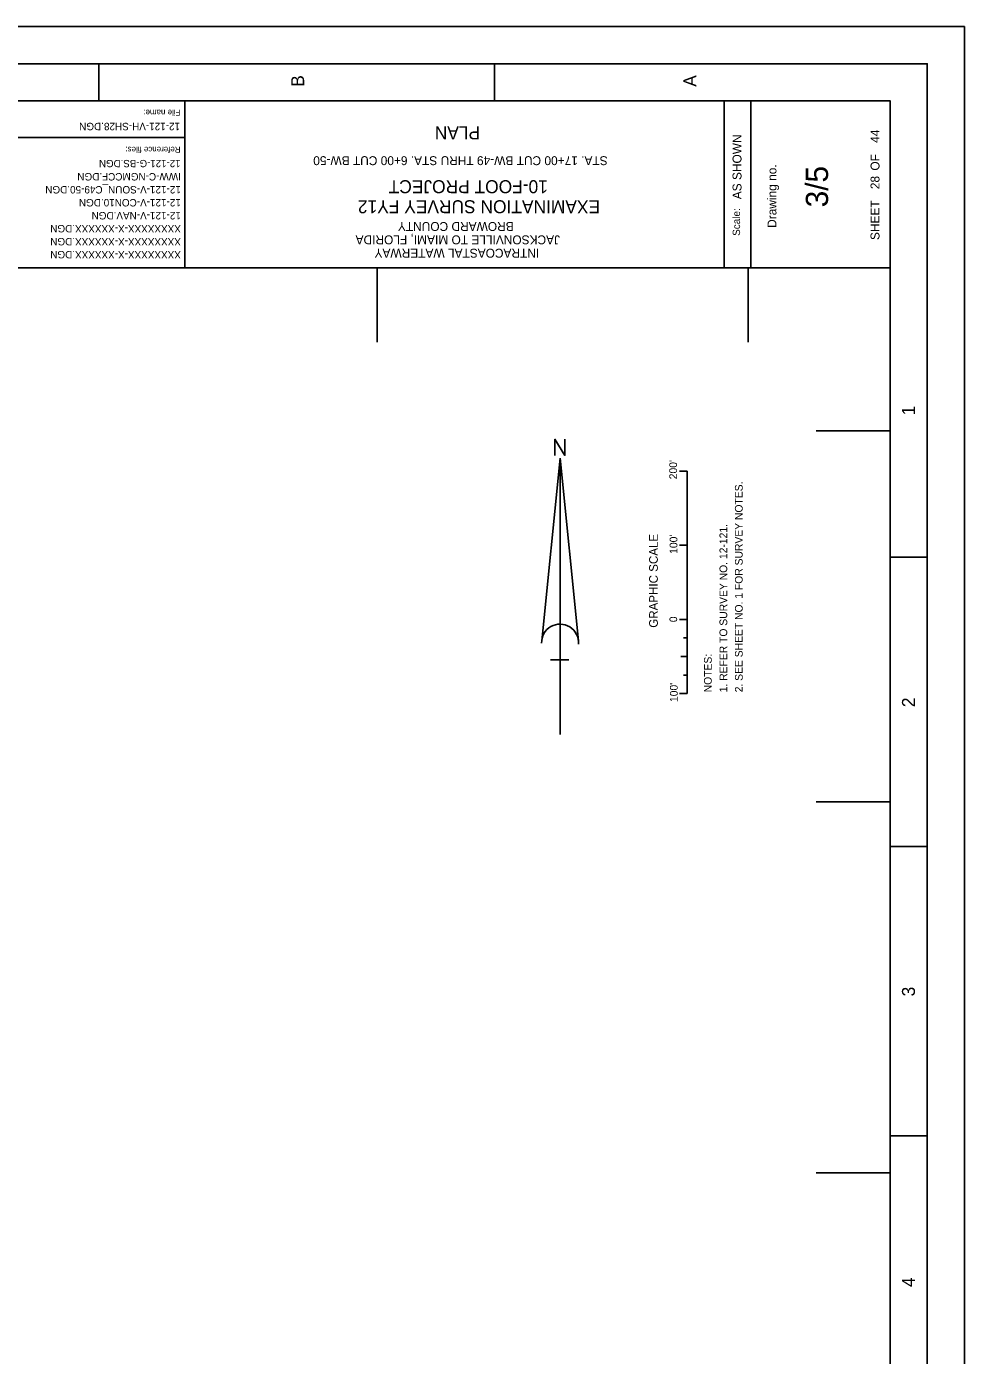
# Model space of a CAD drawing. Extents: x 943892 to 947291, y 640645 to 645045.
# Drawn here: x 946027 to 947291, y 643254 to 645045 of the extents above; entities that cross this region are included whole.
import ezdxf

# ---------------------------------------------------------------- set-up
doc = ezdxf.new("R2010")
doc.units = 0
for name, color, linetype in [('G-ANNO-NPLT', 7, 'Continuous'), ('G-ANNO-TEXT-DRWG', 7, 'Continuous'), ('G-ANNO-TEXT-PROJ', 7, 'Continuous'), ('G-ANNO-TEXT-TTLB', 7, 'Continuous'), ('G-ANNO-TTLB', 7, 'Continuous'), ('V-ANNO-NOTE', 7, 'Continuous'), ('V-ANNO-SYMB', 7, 'Continuous'), ('V-TOPO-COOR-STAT', 7, 'Continuous')]:
    doc.layers.add(name, color=color, linetype=linetype)

msp = doc.modelspace()

# ---------------------------------------------------------------- linework, layer by layer
at = {"layer": 'G-ANNO-NPLT'}
msp.add_lwpolyline([(943891.5, 640644.6), (943891.5, 645044.6), (947291.5, 645044.6), (947291.5, 640644.6)], close=True, dxfattribs=at)
msp.add_lwpolyline([(947241.5, 645044.7), (947291.5, 645044.7), (947291.5, 644994.7)], dxfattribs=at)
at = {"layer": 'G-ANNO-TTLB'}
for p, q in [((946124.9, 644994.6), (946124.9, 644944.6)), ((946658.2, 644994.6), (946658.2, 644944.6)), ((946240.7, 644719.6), (946240.7, 644944.6)), ((946967.7, 644719.6), (946967.7, 644944.6)), ((947003.4, 644719.6), (947003.4, 644944.6)), ((945889.4, 644895.3), (946240.7, 644895.3)), ((943991.5, 644719.6), (947191.5, 644719.6)), ((947241.5, 644329.6), (947191.5, 644329.6)), ((947241.5, 643939.6), (947191.5, 643939.6)), ((947241.5, 643549.6), (947191.5, 643549.6))]:
    msp.add_line(p, q, dxfattribs=at)
for points in [[(947241.5, 640694.6), (947241.5, 644994.6), (943941.5, 644994.6), (943941.5, 640694.6)], [(943991.5, 644944.6), (943991.5, 640819.6), (947191.5, 640819.6), (947191.5, 644944.6)]]:
    msp.add_lwpolyline(points, close=True, dxfattribs=at)
at = {"layer": 'V-ANNO-NOTE'}
for p, q in [((946917.7, 644445.7), (946907.3, 644445.7)), ((946917.7, 644145.7), (946917.7, 644445.7)), ((946917.7, 644345.7), (946907.3, 644345.7)), ((946917.7, 644245.7), (946907.3, 644245.7)), ((946917.7, 644245.7), (946907.3, 644245.7)), ((946917.7, 644245.7), (946912.7, 644245.7)), ((946917.7, 644220.7), (946912.9, 644220.7)), ((946917.7, 644195.7), (946909.2, 644195.7)), ((946917.7, 644170.7), (946912.9, 644170.7)), ((946917.7, 644145.7), (946907.3, 644145.7))]:
    msp.add_line(p, q, dxfattribs=at)
at = {"layer": 'V-ANNO-SYMB'}
for p, q in [((946721.7, 644217.1), (946746.4, 644462.9)), ((946746.4, 644090.5), (946746.4, 644462.9)), ((946771.1, 644217.1), (946746.4, 644462.9)), ((946758.2, 644191.1), (946733.4, 644191.1))]:
    msp.add_line(p, q, dxfattribs=at)
msp.add_lwpolyline([(946739.6, 644466.8), (946739.6, 644488.6), (946753.1, 644466.8), (946753.1, 644488.6)], dxfattribs=at)
msp.add_arc((946746.4, 644214.6), 24.8, 355.2984, 182.0673, dxfattribs=at)
at = {"layer": 'V-TOPO-COOR-STAT'}
for p, q in [((946500, 644619.6), (946500, 644719.6)), ((947000, 644619.6), (947000, 644719.6)), ((947191.5, 644500), (947091.5, 644500)), ((947191.5, 644000), (947091.5, 644000)), ((947191.5, 643500), (947091.5, 643500))]:
    msp.add_line(p, q, dxfattribs=at)

# ---------------------------------------------------------------- texts
at = {"layer": 'G-ANNO-TEXT-DRWG'}
for s, height, rotation, p in [('12-121-VH-SH28.DGN', 10, 180, (946234.3, 644915)), ('PLAN', 17.5, 180, (946638.7, 644910.2)), (' 28          44', 12, 90, (947177, 644821.1)), ('STA. 17+00 CUT BW-49 THRU STA. 6+00 CUT BW-50', 12, 180, (946810.6, 644870)), ('3/5', 30, 90, (947107.7, 644801.1)), ('12-121-V-SOUN_C49-50.DGN', 10, 180, (946235.4, 644829.8)), ('IWW-C-NGMCCF.DGN', 10, 180, (946235.4, 644847.3)), ('12-121-V-CON10.DGN', 10, 180, (946235.4, 644812.3)), ('12-121-V-NAV.DGN', 10, 180, (946235.4, 644794.8)), ('XXXXXXXX-X-XXXXXX.DGN', 10, 180, (946235.4, 644777.3)), ('XXXXXXXX-X-XXXXXX.DGN', 10, 180, (946235.4, 644759.8)), ('XXXXXXXX-X-XXXXXX.DGN', 10, 180, (946235.4, 644742.3))]:
    msp.add_text(s, height=height, rotation=rotation, dxfattribs=at).set_placement(p)
at = {"layer": 'G-ANNO-TEXT-PROJ'}
for s, height, p in [('12-121-G-BS.DGN', 9.8, (946235, 644865)), ('10-FOOT PROJECT', 17.5, (946730, 644837.7)), ('EXAMINATION SURVEY FY12', 17.5, (946800.4, 644810.7)), ('BROWARD COUNTY', 12, (946683.9, 644781.3)), ('JACKSONVILLE TO MIAMI, FLORIDA', 12, (946746.4, 644763.3)), ('INTRACOASTAL WATERWAY', 12, (946718.4, 644745.3))]:
    msp.add_text(s, height=height, rotation=180, dxfattribs=at).set_placement(p)
at = {"layer": 'G-ANNO-TEXT-TTLB'}
for s, height, rotation, p in [('File name:', 8, 180, (946234.7, 644932.7)), ('AS SHOWN', 12, 90, (946991, 644812)), ('Reference files:', 8, 180, (946234.9, 644882.7)), ('SHEET         OF', 12, 90, (947177, 644757)), ('Drawing no.', 12, 90, (947038.1, 644773.4)), ('Scale:', 10, 90, (946989.1, 644762.7))]:
    msp.add_text(s, height=height, rotation=rotation, dxfattribs=at).set_placement(p)
at = {"layer": 'G-ANNO-TTLB'}
for s, p in [('B', (946401.6, 644963.6)), ('A', (946930.3, 644963.6)), ('1', (947224.8, 644520.7)), ('2', (947224.8, 644127.5)), ('3', (947224.8, 643737.7)), ('4', (947224.8, 643345.9))]:
    msp.add_text(s, height=17.5, rotation=90, dxfattribs=at).set_placement(p)
at = {"layer": 'V-ANNO-NOTE'}
for s, height, p in [("200'", 10.42, (946904.1, 644434.6)), ('2. SEE SHEET NO. 1 FOR SURVEY NOTES.', 10.416, (946992.6, 644147.5)), ('1. REFER TO SURVEY NO. 12-121.', 10.416, (946971.8, 644147.5)), ('GRAPHIC SCALE', 11.666, (946878.2, 644234.5)), ("100'", 10.42, (946904.6, 644334.1)), ('0', 10.4, (946904.3, 644242)), ('NOTES:', 10.42, (946950.9, 644147.5)), ("100'", 10.42, (946905, 644134.4))]:
    msp.add_text(s, height=height, rotation=90, dxfattribs=at).set_placement(p)

doc.saveas('drawing.dxf')
